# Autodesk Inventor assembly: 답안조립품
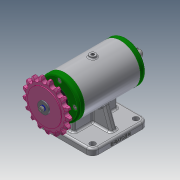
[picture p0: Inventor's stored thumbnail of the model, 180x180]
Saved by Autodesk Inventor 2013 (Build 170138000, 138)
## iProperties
Created: 2019-06
Part Number: 답안조립품
Document SubType Name: Assembly
Designer: a
Author: a
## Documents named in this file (11)
- C:\Users\a\Desktop\490604V1007\답안조립품.iam
- C:\Users\a\Desktop\490604V1007\본체.ipt
- C:\Users\a\Desktop\490604V1007\베어링 6203.ipt
- C:\Users\a\Desktop\490604V1007\볼트 M4.ipt
- C:\Users\a\Desktop\490604V1007\스프로킷.ipt
- C:\Users\a\Desktop\490604V1007\스프링와셔.ipt
- C:\Users\a\Desktop\490604V1007\오일 실 17 30 5.ipt
- C:\Users\a\Desktop\490604V1007\축.ipt
- C:\Users\a\Desktop\490604V1007\커버.ipt
- C:\Users\a\Desktop\490604V1007\키 4x4x12.ipt
- C:\Users\a\Desktop\490604V1007\평와셔.ipt
